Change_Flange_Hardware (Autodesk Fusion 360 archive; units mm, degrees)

design "Change_Flange_Hardware" references "Countersunk Flat Head Screw DIN 965 - M10 x 20 - H Steel 4.6 Plain"
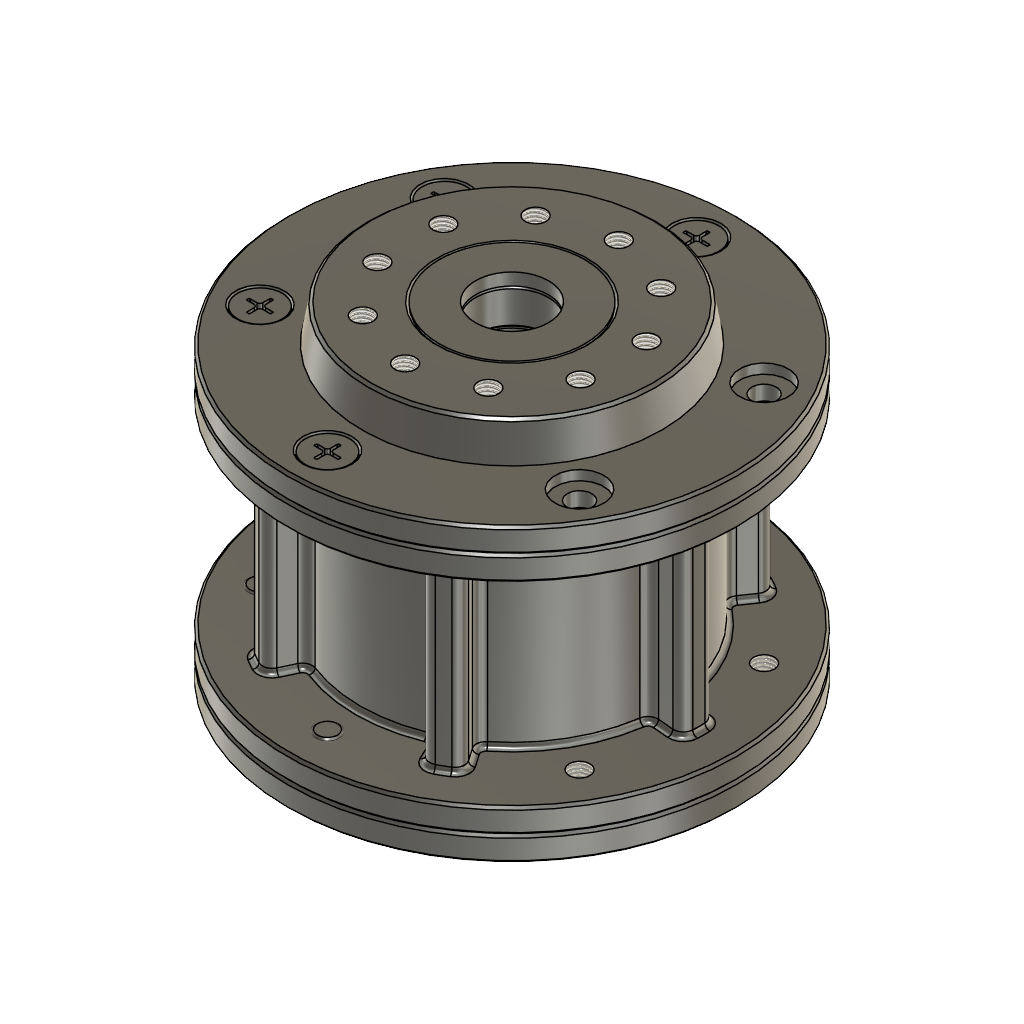
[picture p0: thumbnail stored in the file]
part number: 2026-09-17-09-26-28-567
part number: 2026-09-17-09-29-55-258
description: Part Number
part number: 2011N133_Oil-Embedded Bronze Thrust Bearing
part number: 2026-09-17-09-34-24-056
part number: 2026-09-17-09-39-27-124
part number: 2026-09-17-09-49-44-118
sketch "Sketch1" plane through (0, 0, 0) normal (0, 1, 0) x axis (1, 0, 0)
  line L1 (0, -25) -> (0, 0)
  line L2 (30, -5) -> (30, 0)
  line L3 (25, -5) -> (30, -5)
  line L4 (25, -20) -> (25, -5)
  line L5 (30, -20) -> (25, -20)
  line L6 (30, -25) -> (30, -20)
  line L7 (59, -25) -> (30, -25)
  line L8 (61.6449, -10) -> (59, -25)
  line L9 (92.5, -10) -> (61.6449, -10)
  line L10 (92.5, 0) -> (92.5, -10)
  line L11 (30, 0) -> (92.5, 0)
  point P1 (0, 0)
  point P2 (0, 0)
  point P3 (0, -25)
  point P4 (30, 0)
  point P5 (30, -5)
  point P12 (92.5, -10)
  point P13 (92.5, 0)
  coincident P1 P2
  vertical L1
  parallel L1 L2
  perpendicular L2 L3
  perpendicular L3 L4
  perpendicular L4 L5
  perpendicular L5 L6
  perpendicular L6 L7
  perpendicular L6 L9
  perpendicular L7 L10
  perpendicular L10 L11
  coincident P1 L11
  coincident P3 L7
  equal L2 L6
  dimension "d1" distance P2 P3 = 25
  dimension "d2" = 60
  dimension "d3" = 60 (= "d2")
  dimension "d4" = 50
  dimension "d5" distance P4 P5 = 5
  dimension "d6" = 185
  dimension "d7" distance P12 P13 = 10
  dimension "d8" angle L8 L9 = 100
  dimension "d9" = 118
revolve "Revolve1" sketch "Sketch1" AlongAngle 360
base_feature "Base Feature"
joint "Assemble" alignAngle 0 alignOffsetX 0 alignOffsetY 0 alignOffsetZ 0
copy_paste "CopyPaste1"
joint "Assemble" alignAngle 0 alignOffsetX 0 alignOffsetY 0 alignOffsetZ 0
sketch "Sketch1" plane through (0, 0, 0) normal (1, 0, 0) x axis (0, 1, 0)
  line L1 (0, 25) -> (0, 0)
  line L2 (22.5, 5) -> (15, 5)
  line L3 (22.5, 20) -> (22.5, 5)
  line L4 (15, 20) -> (22.5, 20)
  line L5 (15, 5) -> (15, 20)
  point P1 (0, 0)
  point P2 (0, 0)
  point P3 (0, 25)
  point P4 (15, 5)
  point P7 (15, 20)
  coincident P1 P2
  vertical L1
  perpendicular L1 L2
  perpendicular L2 L3
  perpendicular L3 L4
  perpendicular L2 L5
  dimension "d19" distance P2 P3 = 25
  dimension "d20" distance P4 P7 = 15
  dimension "d21" = 30
  dimension "d22" = 45
  dimension "d23" distance P1 L2 = 5
revolve "Revolve1" sketch "Sketch1" AlongAngle 360
chamfer "Chamfer1" distance 1
chamfer "Chamfer1" distance 1
sketch "Sketch2" plane through (0, 0, 10) normal (0, 0, 1) x axis (-1, 0, 0)
  circle C1 centre (0, 0) radius 61.6449
  circle C2 centre (0, 0) radius 91.5
  circle C3 centre (0, 0) radius 76
  point P4 (0, -76)
  point P3 (0, 0)
  concentric C1 C3
  coincident C3 P4
  vertical P3 P4
  dimension "d28" diameter C3 = 152
hole "Hole1" HoleDiameter 10 TipAngle 118 CBDepth 4 CBDiameter 20
circular_pattern "C-Pattern1" TotalAngle 360
sketch "Sketch1" plane through (0, 0, 0) normal (0, 1, 0) x axis (1, 0, 0)
  line L1 (0, 100) -> (0, 0)
  line L2 (92.5, 0) -> (44, 0)
  line L3 (92.5, 10) -> (92.5, 0)
  line L4 (62.5, 10) -> (92.5, 10)
  line L5 (62.5, 90) -> (62.5, 10)
  line L6 (92.5, 90) -> (62.5, 90)
  line L7 (92.5, 100) -> (92.5, 90)
  line L8 (44, 100) -> (92.5, 100)
  line L9 (44, 0) -> (44, 100)
  point P1 (0, 0)
  point P2 (0, 0)
  point P3 (0, 100)
  point P5 (92.5, 0)
  point P6 (92.5, 10)
  coincident P1 P2
  vertical L1
  perpendicular L1 L2
  perpendicular L2 L3
  perpendicular L3 L4
  perpendicular L4 L5
  perpendicular L5 L6
  perpendicular L6 L7
  perpendicular L7 L8
  perpendicular L2 L9
  coincident P1 L2
  coincident P3 L8
  equal L3 L7
  collinear L3 L7
  dimension "d35" distance P2 P3 = 100
  dimension "d36" = 88
  dimension "d37" = 125
  dimension "d38" = 185
  dimension "d39" distance P5 P6 = 10
revolve "Revolve1" sketch "Sketch1" AlongAngle 360
chamfer "Chamfer1" distance 1
sketch "Sketch2" plane through (0, 0, 0) normal (0, 0, 1) x axis (-1, 0, 0)
  circle C1 centre (0, 0) radius 44
  circle C2 centre (0, 0) radius 91.5
  circle C3 centre (0, 0) radius 76
  point P4 (0, -76)
  point P3 (0, 0)
  concentric C1 C3
  coincident C3 P4
  vertical P3 P4
  dimension "d42" diameter C3 = 152
hole "Hole1" HoleDiameter 8.526 TipAngle 118
circular_pattern "C-Pattern1" TotalAngle 360
chamfer "Chamfer2" distance 5
sketch "Sketch3" plane through (0, 0, 0) normal (0, 1, 0) x axis (1, 0, 0)
  line L1 (62.5, 10) -> (91.5, 10)
  line L2 (-91.5, 10) -> (-62.5, 10)
  line L3 (62.5, 90) -> (62.5, 10)
  line L4 (-62.5, 10) -> (-62.5, 90)
  line L5 (-62.5, 90) -> (-91.5, 90)
  line L6 (91.5, 90) -> (62.5, 90)
  line L7 (-77, 90) -> (-77, 10)
  point P14 (-77, 10)
  point P15 (-77, 90)
  midpoint L2 P14
  midpoint L5 P15
revolve "Revolve2" sketch "Sketch3" AlongAngle 5 AgainstAngle 5
fillet "Fillet1" radius 4
circular_pattern "C-Pattern2" TotalAngle 360
fillet "Fillet2" radius 2
sketch "Sketch4" plane through (0, 0, -100) normal (0, 0, -1) x axis (1, 0, 0)
  circle C1 centre (0, 0) radius 91.5
  circle C2 centre (0, 0) radius 49
  circle C3 centre (0, -76) radius 4.263
hole "Hole2" HoleDiameter 8.526 TipAngle 118
circular_pattern "C-Pattern3" TotalAngle 360
sketch "Sketch3" plane through (0, 0, 25) normal (0, 0, 1) x axis (-1, 0, 0)
  circle C1 centre (0, 0) radius 58
  circle C2 centre (0, 0) radius 31
  circle C3 centre (0, 0) radius 44
  point P4 (0, 44)
  point P3 (0, 0)
  concentric C1 C3
  coincident C3 P4
  vertical P3 P4
  dimension "d64" diameter C3 = 88
hole "Hole2" HoleDepth 18 HoleDiameter 8.526 TipAngle 118
circular_pattern "C-Pattern2" countU 10 TotalAngle 360
copy_paste "CopyPaste2"
copy_paste "CopyPaste3"
copy_paste "CopyPaste4"
copy_paste "CopyPaste5"
as_built_joint "As-built1"
step "GeometricRelationship" Offset 0 Offset 0 Angle 0
as_built_joint "As-built2"
sketch "Sketch1" plane through (0, 0, 0) normal (1, 0, 0) x axis (0, 1, 0)
  line L1 (0, -100) -> (0, 0)
  line L2 (15, -100) -> (15, 0)
  line L3 (25, -100) -> (15, -100)
  line L4 (25, -55) -> (25, -100)
  line L5 (44, -55) -> (25, -55)
  line L6 (44, -45) -> (44, -55)
  line L7 (25, -45) -> (44, -45)
  line L8 (25, 0) -> (25, -45)
  line L9 (15, 0) -> (25, 0)
  line L10 (44, -50) -> (0, -50)
  point P1 (0, 0)
  point P2 (0, 0)
  point P3 (0, -100)
  point P12 (0, -50)
  point P13 (44, -50)
  point P8 (44, -55)
  point P9 (44, -45)
  coincident P1 P2
  vertical L1
  parallel L1 L2
  perpendicular L2 L3
  perpendicular L3 L4
  perpendicular L2 L5
  perpendicular L5 L6
  perpendicular L6 L7
  perpendicular L7 L8
  perpendicular L2 L9
  coincident P1 L9
  coincident P3 L3
  collinear L4 L8
  midpoint L1 P12
  midpoint L6 P13
  horizontal L10
  dimension "d75" distance P2 P3 = 100
  dimension "d76" = 30
  dimension "d77" = 50
  dimension "d78" distance P8 P9 = 10
  dimension "d79" = 88
revolve "Revolve1" sketch "Sketch1" AlongAngle 360
chamfer "Chamfer1" distance 1
fillet "Fillet1" radius 5
step "Screw1"
joint "Assemble" alignAngle 0 alignOffsetX 0 alignOffsetY 0 alignOffsetZ 7.5
step "Screw2"
joint "Assemble" alignAngle 0 alignOffsetX 0 alignOffsetY 0 alignOffsetZ 7.5
step "Screw3"
joint "Assemble" alignAngle 0 alignOffsetX 0 alignOffsetY 0 alignOffsetZ 7.5
step "Screw4"
joint "Assemble" alignAngle 0 alignOffsetX 0 alignOffsetY 0 alignOffsetZ 7.5
step "Screw5"
joint "Assemble" alignAngle 0 alignOffsetX 0 alignOffsetY 0 alignOffsetZ 7.5
step "Screw6"
joint "Assemble" alignAngle 0 alignOffsetX 0 alignOffsetY 0 alignOffsetZ 7.5
step "Screw7"
joint "Assemble" alignAngle 0 alignOffsetX 0 alignOffsetY 0 alignOffsetZ 7.5
step "Screw8"
joint "Assemble" alignAngle 0 alignOffsetX 0 alignOffsetY 0 alignOffsetZ 7.5
step "Screw9"
joint "Assemble" alignAngle 0 alignOffsetX 0 alignOffsetY 0 alignOffsetZ 7.5
step "Screw10"
joint "Assemble" alignAngle 0 alignOffsetX 0 alignOffsetY 0 alignOffsetZ 7.5
step "Screw11"
joint "Assemble" alignAngle 0 alignOffsetX 0 alignOffsetY 0 alignOffsetZ 7.5
step "Screw12"
joint "Assemble" alignAngle 0 alignOffsetX 0 alignOffsetY 0 alignOffsetZ 7.5
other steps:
chamfer "Chamfer1" distance 1
thread "Thread1" ThreadOffset 0 ThreadDepth 7.4
thread "Thread1" ThreadOffset 0 ThreadDepth 7.4
thread "Thread2" ThreadOffset 0 ThreadDepth 7.4
create_component "CreateComponent1"
create_component "CreateComponent2"
joint_origin "JointOrigin1"
joint_origin "JointOrigin1"
joint_origin "JointOrigin2"
joint_origin "JointOrigin2"
create_component "CreateComponent3"
create_component "CreateComponent4"
create_component "CreateComponent5"
joint_origin "JointOrigin3"
joint_origin "JointOrigin4"
joint_origin "JointOrigin5"
joint_origin "JointOrigin6"
joint_origin "JointOrigin7"
joint_origin "JointOrigin8"
joint_origin "JointOrigin9"
joint_origin "JointOrigin10"
joint_origin "JointOrigin11"
joint_origin "JointOrigin12"
joint_origin "JointOrigin13"
joint_origin "JointOrigin14"

design "Countersunk Flat Head Screw DIN 965 - M10 x 20 - H Steel 4.6 Plain"
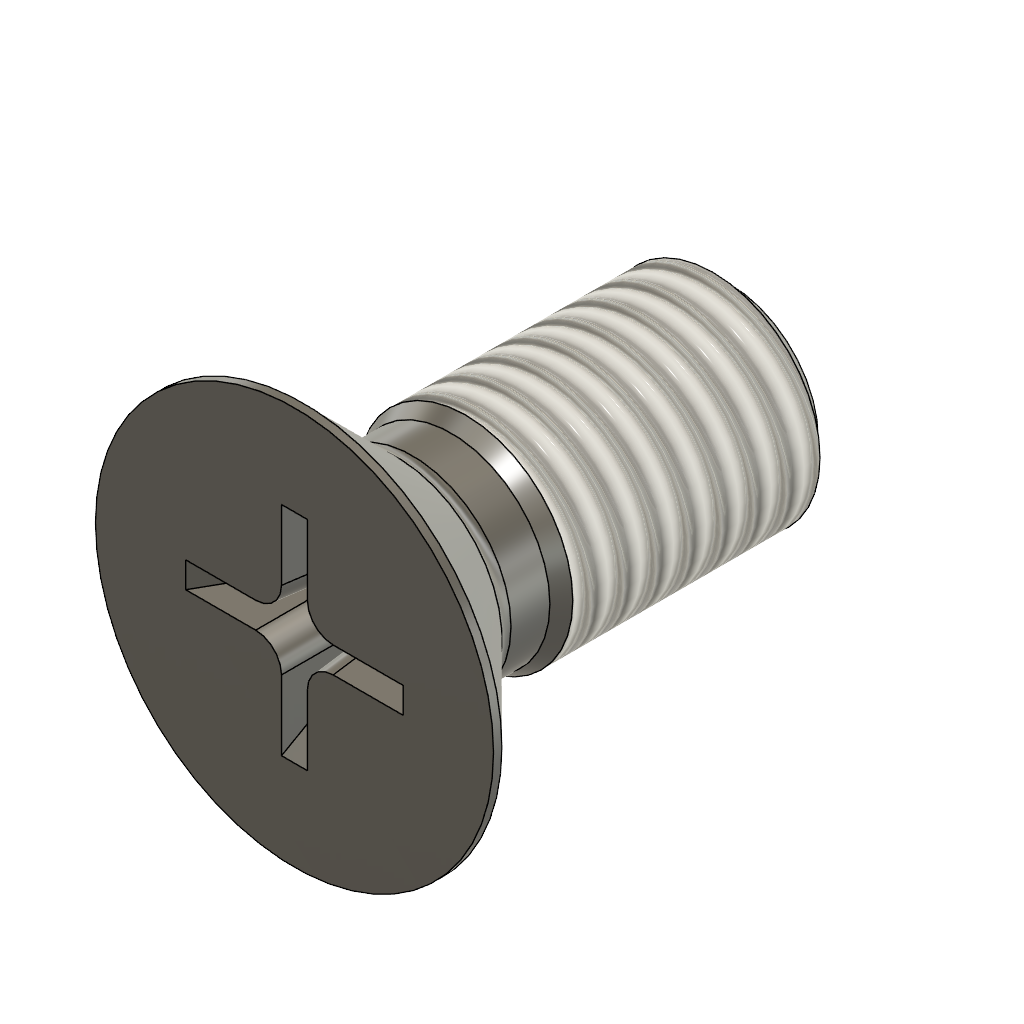
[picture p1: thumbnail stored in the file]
description: Countersunk Flat Head Screw DIN 965 - M10 x 20 - H
part number: DIN 965 - M10 x 20 - H Steel 4.6 Plain
parameter "adsk_nomlen" = 20
parameter "adsk_headh" = 5
parameter "adsk_headdia" = 18.3
parameter "adsk_nomdia" = 10
parameter "adsk_headang" = 90
parameter "adsk_phildia" = 10
parameter "adsk_philwidth" = 1.19
parameter "adsk_phildepth" = 5.7
parameter "adsk_shnkdia" = 9.0798
parameter "adsk_thrlen" = 12
parameter "adsk_pitch1" = 1.5
parameter "adsk_startlen" = 0.9202
parameter "adsk_midfillet" = 1 (= "adsk_nomdia * 0.1")
parameter "adsk_endpointdia" = 8.1596
sketch "Sketch1" plane through (0, 0, 0) normal (0, 1, 0) x axis (1, 0, 0)
  line L1 (-9.15, -9.5399) -> (0, -9.5399)
  line L2 (-9.15, -9.15) -> (-9.15, -9.5399)
  line L3 (-4.5399, -4.5399) -> (-9.15, -9.15)
  line L4 (-5, 10.4601) -> (-5, -1.5399)
  line L5 (0, 10.4601) -> (-5, 10.4601)
  line L6 (0, -9.5399) -> (0, 10.4601)
  line L7 (-4.5399, -4.5399) -> (-4.5399, -2.3368)
  line L8 (-4.5399, -2.3368) -> (-5, -1.5399)
  point P1 (0, 0)
  point P2 (0, -9.5399)
  point P7 (0, 10.4601)
  point P5 (-4.5399, -4.5399)
  point P10 (-4.5399, -4.5399)
  point P11 (-4.5399, -2.3368)
  point P9 (-4.5399, -2.3368)
  point P8 (-5, -1.5399)
  perpendicular L1 L2
  vertical L4
  perpendicular L4 L5
  perpendicular L1 L6
  collinear P1 P2 P7
  horizontal L1
  coincident P5 P10
  coincident L7 P11
  coincident P9 P11
  coincident P1 L3
  dimension "d9" = 10 (= "adsk_nomdia")
  dimension "d11" = 18.3 (= "adsk_headdia")
  dimension "d71" distance L1 P5 = 5 (= "adsk_headh")
  dimension "d72" = 9.0798 (= "adsk_shnkdia")
  dimension "d89" distance L5 P8 = 12 (= "adsk_thrlen")
  dimension "d101" angle L4 L8 = 30
  dimension "d115" distance P2 L5 = 20 (= "adsk_nomlen")
  dimension "d121" angle L3 L6 = 45 (= "adsk_headang * 0.5")
revolve "Revolve1" sketch "Sketch1" AlongAngle 360
sketch "Sketch2" plane through (0, 0, 9.5399) normal (0, 0, 1) x axis (1, 0, 0)
  line L1 (-5, 0.595) -> (-0.595, 0.595)
  line L2 (-5, -0.595) -> (-5, 0.595)
  line L3 (-0.595, -0.595) -> (-5, -0.595)
  line L4 (0.595, -0.595) -> (0.595, -5)
  line L5 (0.595, -5) -> (-0.595, -5)
  line L6 (-0.595, -5) -> (-0.595, -0.595)
  line L7 (0.595, 0.595) -> (5, 0.595)
  line L8 (5, 0.595) -> (5, -0.595)
  line L9 (5, -0.595) -> (0.595, -0.595)
  line L10 (-0.595, 0.595) -> (-0.595, 5)
  line L11 (-0.595, 5) -> (0.595, 5)
  line L12 (0.595, 5) -> (0.595, 0.595)
  point P2 (-0.595, 0.595)
  point P5 (-0.595, -0.595)
  point P15 (-0.595, 0.595)
  point P8 (-0.595, -5)
  horizontal L1
  perpendicular L1 L2
  vertical P2 P5
  coincident P2 P15
  dimension "d117" distance P8 L11 = 10 (= "adsk_phildia")
  dimension "d122" distance L1 L3 = 1.19 (= "adsk_philwidth")
  dimension "d111" C-Pattern1-Angle = 360
extrude "Extrude1" new body sketch "Sketch2" no distance stored taper -4
draft "Draft1" Angle1 30 Angle2 0
fillet "Fillet3" radius 1.19 (= "adsk_philwidth")
combine "Combine1"
thread "Thread1" ThreadOffset 0 ThreadLength 10
fillet "Fillet5" radius 1 (= "adsk_midfillet")
sketch "Sketch6" plane through (0, 0, 0) normal (0, 1, 0) x axis (1, 0, 0)
  line L1 (-5.1, 10.4601) -> (-4.0798, 10.4601)
  line L2 (-5.1, 9.5399) -> (-5.1, 10.4601)
  line L3 (-4.0798, 10.4601) -> (-5.1, 9.5399)
  line L4 (0, 10.4601) -> (-5, 10.4601)
  line L5 (0, 10.4601) -> (0, 0)
  point P4 (-4.0798, 10.4601)
  point P1 (0, 0)
  point P7 (0, 0)
  point P6 (0, 10.4601)
  point P8 (0, 10.4601)
  point P3 (-5.1, 9.5399)
  horizontal L1
  perpendicular L1 L2
  coincident P4 L4
  coincident P1 P7
  coincident P6 P8
  dimension "d102" distance P1 L2 = 5.1 (= "adsk_nomdia * 0.51")
  dimension "d118" distance P4 L5 = 4.0798 (= "adsk_endpointdia / 2")
  dimension "d119" distance L1 P3 = 0.9202 (= "adsk_startlen")
revolve "Revolve3" sketch "Sketch6" AlongAngle 360
joint_origin "JointOrigin3" OffsetX 0 OffsetY 0 OffsetZ 0 AngleZ 0
joint_origin "JointOrigin4" OffsetX 0 OffsetY 0 OffsetZ 9.5399 (= "( adsk_shnkdia / 2 ) * tan(90 deg - adsk_headang / 2) + adsk_headh") AngleZ 0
